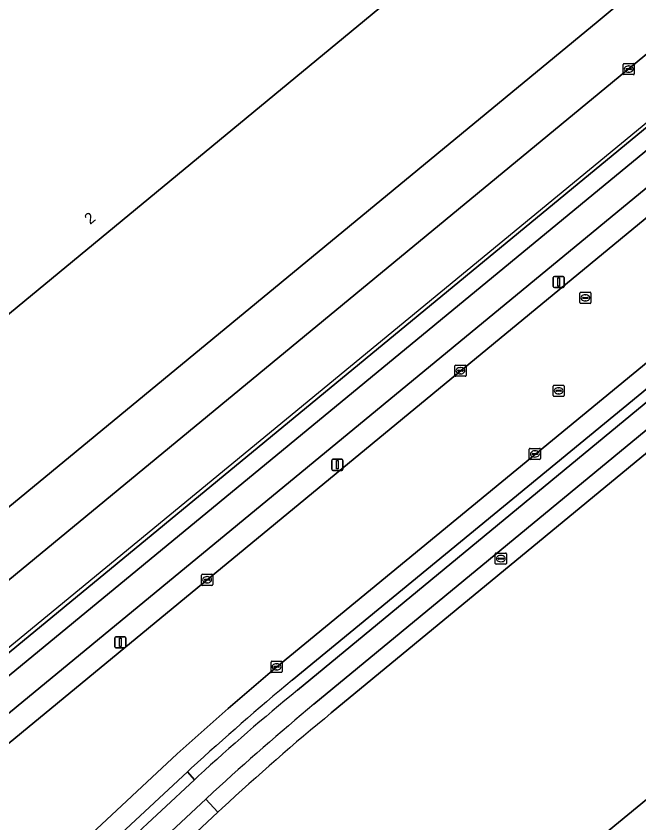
# Model space of a CAD drawing. Extents: x 156141 to 158132, y 385651 to 388333.
# Drawn here: x 157302.8 to 157358.7, y 386521.5 to 386593.9 of the extents above; entities that cross this region are included whole.
import ezdxf

# ---------------------------------------------------------------- set-up
doc = ezdxf.new("R2010")
doc.units = 0
for name, color, linetype in [('IMGEO_Berm_groen', 7, 'Continuous'), ('IMGEO_Berm_open', 7, 'Continuous'), ('IMGEO_Brandkraan', 7, 'Continuous'), ('IMGEO_Erf', 7, 'Continuous'), ('IMGEO_Fietspad_gesloten', 7, 'Continuous'), ('IMGEO_Hek', 7, 'Continuous'), ('IMGEO_Kolk', 7, 'Continuous'), ('IMGEO_Lichtmast', 7, 'Continuous'), ('IMGEO_Pand', 7, 'Continuous'), ('IMGEO_Pand_nummerreeks', 7, 'Continuous'), ('IMGEO_Parkeervlak_open', 7, 'Continuous'), ('IMGEO_Rijbaan_lokaal_gesloten', 7, 'Continuous'), ('IMGEO_Rioolput', 7, 'Continuous'), ('IMGEO_Voetpad_open', 7, 'Continuous')]:
    doc.layers.add(name, color=color, linetype=linetype)

msp = doc.modelspace()

# ---------------------------------------------------------------- linework, layer by layer
at = {"layer": 'IMGEO_Berm_groen'}
msp.add_lwpolyline([(157382.602, 386594.939), (157381.274, 386596.535), (157296.442, 386526.682), (157297.766, 386525.075)], close=True, dxfattribs=at)
at = {"layer": 'IMGEO_Berm_open'}
for points in [[(157328.045, 386533.38), (157394.438, 386588.131)], [(157376.34, 386574.366), (157372.407, 386571.122), (157327.556, 386534.294)], [(157318.496, 386526.391), (157318.148, 386526.066), (157318.786, 386525.342), (157319.149, 386525.681)]]:
    msp.add_lwpolyline(points, dxfattribs=at)
msp.add_lwpolyline([(157318.786, 386525.342), (157318.148, 386526.066), (157312.211, 386520.524), (157312.866, 386519.814)], close=True, dxfattribs=at)
for centre, radius, start, end in [((157539.191, 386282.531), 328.898, 130.0508, 132.14531), ((157438.082, 386397.245), 175.045, 128.94858, 132.8002)]:
    msp.add_arc(centre, radius, start, end, dxfattribs=at)
at = {"layer": 'IMGEO_Brandkraan'}
for p, q in [((157345.805, 386544.773), (157345.805, 386545.625)), ((157345.88, 386545.699), (157346.732, 386545.699)), ((157346.293, 386545.479), (157346.318, 386545.479)), ((157346.806, 386545.625), (157346.806, 386544.773)), ((157346.732, 386544.699), (157345.88, 386544.699)), ((157346.064, 386545.193), (157346.064, 386545.205)), ((157346.502, 386545.156), (157346.104, 386545.156)), ((157346.107, 386545.242), (157346.505, 386545.242)), ((157346.316, 386544.919), (157346.291, 386544.919)), ((157346.548, 386545.205), (157346.548, 386545.193))]:
    msp.add_line(p, q, dxfattribs=at)
for points in [[(157345.805, 386544.773), (157345.805, 386545.625)], [(157345.88, 386545.699), (157346.732, 386545.699)], [(157346.806, 386545.625), (157346.806, 386544.773)], [(157346.732, 386544.699), (157345.88, 386544.699)]]:
    msp.add_lwpolyline(points, dxfattribs=at)
for centre, radius, start, end in [((157345.882, 386545.623), 0.0765, 91.55205, 178.44795), ((157345.882, 386545.623), 0.0765, 91.55205, 178.44795), ((157346.73, 386545.623), 0.0765, 1.55205, 88.44795), ((157346.73, 386545.623), 0.0765, 1.55205, 88.44795), ((157345.882, 386544.775), 0.0765, 181.55205, 268.44795), ((157345.882, 386544.775), 0.0765, 181.55205, 268.44795), ((157346.104, 386545.202), 0.0403, 85.87752, 175.75265), ((157346.101, 386545.192), 0.0366, 178.93798, 274.71019), ((157346.505, 386545.199), 0.043, 264.86636, 352.45326), ((157346.509, 386545.204), 0.0386, 1.73085, 96.63898), ((157346.73, 386544.775), 0.0765, 271.55205, 358.44795), ((157346.73, 386544.775), 0.0765, 271.55205, 358.44795)]:
    msp.add_arc(centre, radius, start, end, dxfattribs=at)
for centre, major_axis, ratio, start_param, end_param in [((157346.292, 386545.199), (-0.387, 0.002), 0.722429, 4.712389, 7.853982), ((157346.317, 386545.199), (-0.39, 0.002), 0.717154, 1.570796, 4.712389)]:
    msp.add_ellipse(centre, major_axis=major_axis, ratio=ratio, start_param=start_param, end_param=end_param, dxfattribs=at)
at = {"layer": 'IMGEO_Erf'}
for points in [[(157305.192, 386652.34), (157328.566, 386623.963), (157330.054, 386625.191), (157333.041, 386621.572), (157326.951, 386616.541), (157327.989, 386615.321), (157327.85, 386615.21), (157325.922, 386617.509), (157324.723, 386616.531), (157326.63, 386614.203), (157339.73, 386598.213), (157295.954, 386562.121), (157267.479, 386596.651), (157267.16, 386597.038), (157261.752, 386592.577), (157272.198, 386579.91), (157282.729, 386567.139), (157237.494, 386529.843)], [(157426.002, 386606.547), (157415.889, 386601.234), (157395.717, 386584.595), (157331.077, 386531.339)], [(157374.788, 386603.209), (157247.853, 386498.572)], [(157244.527, 386502.398), (157355.06, 386593.473), (157357.572, 386595.586)], [(157227.04, 386499.657), (157223.804, 386503.613), (157223.415, 386503.292), (157220.027, 386500.497), (157216.845, 386504.354), (157216.725, 386504.499), (157208.034, 386497.245), (157213.099, 386491.073), (157226.605, 386474.613), (157226.82, 386474.791), (157233.891, 386480.604), (157236.032, 386482.364), (157257.451, 386500), (157293.78, 386529.914), (157370.157, 386592.804)], [(157297.7, 386472.957), (157408.986, 386564.286), (157406.345, 386567.501), (157408.054, 386569.305), (157409.595, 386570.572), (157409.296, 386570.978), (157413.216, 386574.145), (157432.072, 386589.667)], [(157321.28, 386522.788), (157320.885, 386522.419), (157315.585, 386517.47), (157309.052, 386511.37), (157296.875, 386500), (157254.307, 386460.253), (157244.415, 386451.012)]]:
    msp.add_lwpolyline(points, dxfattribs=at)
msp.add_arc((157459.556, 386374.251), 202.937, 129.27903, 132.95107, dxfattribs=at)
at = {"layer": 'IMGEO_Fietspad_gesloten'}
for points in [[(157329.519, 386532.125), (157395.183, 386586.243), (157420.831, 386607.378), (157421.754, 386607.263), (157440.244, 386622.337), (157440.347, 386623.46), (157455.216, 386635.714), (157460.748, 386640.332), (157459.614, 386641.71), (157440.559, 386626.134), (157436.323, 386622.672), (157424.344, 386612.801), (157418.226, 386607.639), (157394.438, 386588.131), (157328.045, 386533.38)], [(157264.038, 386500), (157296.442, 386526.682), (157381.274, 386596.535), (157379.639, 386598.545), (157294.792, 386528.687), (157259.949, 386500), (157236.74, 386480.891), (157225.904, 386471.963), (157216.572, 386464.306), (157144.792, 386405.245)], [(157319.149, 386525.681), (157318.786, 386525.342), (157312.866, 386519.814), (157306.779, 386514.131), (157291.645, 386500), (157251.933, 386462.92), (157239.857, 386451.669), (157234.331, 386446.076), (157226.974, 386437.945), (157221.6, 386431.989), (157216.385, 386426.46), (157218.105, 386424.875), (157235.961, 386444.744)], [(157242.992, 386451.871), (157253.209, 386461.424), (157294.518, 386500), (157308.027, 386512.615), (157314.484, 386518.644), (157319.804, 386523.613), (157320.476, 386524.24)]]:
    msp.add_lwpolyline(points, dxfattribs=at)
for centre, radius, start, end in [((157438.082, 386397.245), 175.045, 128.94858, 132.8002), ((157491.803, 386336.88), 253.883, 129.73269, 132.4406)]:
    msp.add_arc(centre, radius, start, end, dxfattribs=at)
at = {"layer": 'IMGEO_Hek'}
msp.add_lwpolyline([(157370.513, 386593.457), (157256.854, 386500)], dxfattribs=at)
at = {"layer": 'IMGEO_Kolk'}
for p, q in [((157357.292, 386588.735), (157357.292, 386589.587)), ((157357.367, 386589.661), (157358.219, 386589.661)), ((157358.293, 386589.587), (157358.293, 386588.735)), ((157357.551, 386589.155), (157357.551, 386589.167)), ((157357.989, 386589.118), (157357.591, 386589.118)), ((157357.594, 386589.204), (157357.992, 386589.204)), ((157357.803, 386588.881), (157357.778, 386588.881)), ((157357.78, 386589.441), (157357.805, 386589.441)), ((157358.035, 386589.167), (157358.035, 386589.155)), ((157358.219, 386588.661), (157357.367, 386588.661)), ((157342.176, 386561.652), (157342.176, 386562.504)), ((157342.251, 386562.578), (157343.103, 386562.578)), ((157342.435, 386562.072), (157342.435, 386562.084)), ((157342.873, 386562.035), (157342.475, 386562.035)), ((157342.478, 386562.121), (157342.876, 386562.121)), ((157342.664, 386562.358), (157342.689, 386562.358)), ((157342.919, 386562.084), (157342.919, 386562.072)), ((157343.177, 386562.504), (157343.177, 386561.652)), ((157343.103, 386561.578), (157342.251, 386561.578)), ((157342.687, 386561.798), (157342.662, 386561.798)), ((157348.863, 386554.178), (157348.863, 386555.03)), ((157348.938, 386555.104), (157349.79, 386555.104)), ((157349.351, 386554.884), (157349.376, 386554.884)), ((157349.864, 386555.03), (157349.864, 386554.178)), ((157349.79, 386554.104), (157348.938, 386554.104)), ((157349.122, 386554.598), (157349.122, 386554.61)), ((157349.56, 386554.561), (157349.162, 386554.561)), ((157349.165, 386554.647), (157349.563, 386554.647)), ((157349.374, 386554.324), (157349.349, 386554.324)), ((157349.606, 386554.61), (157349.606, 386554.598)), ((157319.418, 386542.876), (157319.418, 386543.728)), ((157319.493, 386543.802), (157320.345, 386543.802)), ((157319.677, 386543.296), (157319.677, 386543.308)), ((157320.115, 386543.259), (157319.717, 386543.259)), ((157319.72, 386543.345), (157320.118, 386543.345)), ((157319.906, 386543.582), (157319.931, 386543.582)), ((157320.161, 386543.308), (157320.161, 386543.296)), ((157320.419, 386543.728), (157320.419, 386542.876)), ((157320.345, 386542.802), (157319.493, 386542.802)), ((157319.929, 386543.022), (157319.904, 386543.022)), ((157325.738, 386535.986), (157326.59, 386535.986)), ((157325.663, 386535.06), (157325.663, 386535.912)), ((157325.922, 386535.48), (157325.922, 386535.492)), ((157326.36, 386535.443), (157325.962, 386535.443)), ((157325.965, 386535.529), (157326.363, 386535.529)), ((157326.174, 386535.206), (157326.149, 386535.206)), ((157326.151, 386535.766), (157326.176, 386535.766)), ((157326.406, 386535.492), (157326.406, 386535.48)), ((157326.664, 386535.912), (157326.664, 386535.06)), ((157326.59, 386534.986), (157325.738, 386534.986))]:
    msp.add_line(p, q, dxfattribs=at)
for points in [[(157357.292, 386588.735), (157357.292, 386589.587)], [(157357.367, 386589.661), (157358.219, 386589.661)], [(157358.293, 386589.587), (157358.293, 386588.735)], [(157358.219, 386588.661), (157357.367, 386588.661)], [(157342.176, 386561.652), (157342.176, 386562.504)], [(157342.251, 386562.578), (157343.103, 386562.578)], [(157343.177, 386562.504), (157343.177, 386561.652)], [(157343.103, 386561.578), (157342.251, 386561.578)], [(157348.863, 386554.178), (157348.863, 386555.03)], [(157348.938, 386555.104), (157349.79, 386555.104)], [(157349.864, 386555.03), (157349.864, 386554.178)], [(157349.79, 386554.104), (157348.938, 386554.104)], [(157319.418, 386542.876), (157319.418, 386543.728)], [(157319.493, 386543.802), (157320.345, 386543.802)], [(157320.419, 386543.728), (157320.419, 386542.876)], [(157320.345, 386542.802), (157319.493, 386542.802)], [(157325.738, 386535.986), (157326.59, 386535.986)], [(157325.663, 386535.06), (157325.663, 386535.912)], [(157326.664, 386535.912), (157326.664, 386535.06)], [(157326.59, 386534.986), (157325.738, 386534.986)]]:
    msp.add_lwpolyline(points, dxfattribs=at)
for centre, radius, start, end in [((157357.369, 386589.585), 0.0765, 91.55205, 178.44795), ((157357.369, 386589.585), 0.0765, 91.55205, 178.44795), ((157358.217, 386589.585), 0.0765, 1.55205, 88.44795), ((157358.217, 386589.585), 0.0765, 1.55205, 88.44795), ((157357.591, 386589.164), 0.0403, 85.87752, 175.75265), ((157357.588, 386589.154), 0.0366, 178.93798, 274.71019), ((157357.992, 386589.161), 0.043, 264.86636, 352.45326), ((157357.996, 386589.166), 0.0386, 1.73085, 96.63898), ((157357.369, 386588.737), 0.0765, 181.55205, 268.44795), ((157357.369, 386588.737), 0.0765, 181.55205, 268.44795), ((157358.217, 386588.737), 0.0765, 271.55205, 358.44795), ((157358.217, 386588.737), 0.0765, 271.55205, 358.44795), ((157342.253, 386562.502), 0.0765, 91.55205, 178.44795), ((157342.253, 386562.502), 0.0765, 91.55205, 178.44795), ((157342.475, 386562.081), 0.0403, 85.87752, 175.75265), ((157342.472, 386562.071), 0.0366, 178.93798, 274.71019), ((157342.876, 386562.078), 0.043, 264.86636, 352.45326), ((157342.88, 386562.083), 0.0386, 1.73085, 96.63898), ((157343.101, 386562.502), 0.0765, 1.55205, 88.44795), ((157343.101, 386562.502), 0.0765, 1.55205, 88.44795), ((157342.253, 386561.654), 0.0765, 181.55205, 268.44795), ((157342.253, 386561.654), 0.0765, 181.55205, 268.44795), ((157343.101, 386561.654), 0.0765, 271.55205, 358.44795), ((157343.101, 386561.654), 0.0765, 271.55205, 358.44795), ((157348.94, 386555.028), 0.0765, 91.55205, 178.44795), ((157348.94, 386555.028), 0.0765, 91.55205, 178.44795), ((157349.788, 386555.028), 0.0765, 1.55205, 88.44795), ((157349.788, 386555.028), 0.0765, 1.55205, 88.44795), ((157348.94, 386554.18), 0.0765, 181.55205, 268.44795), ((157348.94, 386554.18), 0.0765, 181.55205, 268.44795), ((157349.162, 386554.607), 0.0403, 85.87752, 175.75265), ((157349.159, 386554.597), 0.0366, 178.93798, 274.71019), ((157349.563, 386554.604), 0.043, 264.86636, 352.45326), ((157349.567, 386554.609), 0.0386, 1.73085, 96.63898), ((157349.788, 386554.18), 0.0765, 271.55205, 358.44795), ((157349.788, 386554.18), 0.0765, 271.55205, 358.44795), ((157319.495, 386543.726), 0.0765, 91.55205, 178.44795), ((157319.495, 386543.726), 0.0765, 91.55205, 178.44795), ((157319.717, 386543.305), 0.0403, 85.87752, 175.75265), ((157319.714, 386543.295), 0.0366, 178.93798, 274.71019), ((157320.118, 386543.302), 0.043, 264.86636, 352.45326), ((157320.122, 386543.307), 0.0386, 1.73085, 96.63898), ((157320.343, 386543.726), 0.0765, 1.55205, 88.44795), ((157320.343, 386543.726), 0.0765, 1.55205, 88.44795), ((157319.495, 386542.878), 0.0765, 181.55205, 268.44795), ((157319.495, 386542.878), 0.0765, 181.55205, 268.44795), ((157320.343, 386542.878), 0.0765, 271.55205, 358.44795), ((157320.343, 386542.878), 0.0765, 271.55205, 358.44795), ((157325.74, 386535.91), 0.0765, 91.55205, 178.44795), ((157325.74, 386535.91), 0.0765, 91.55205, 178.44795), ((157326.588, 386535.91), 0.0765, 1.55205, 88.44795), ((157326.588, 386535.91), 0.0765, 1.55205, 88.44795), ((157325.962, 386535.489), 0.0403, 85.87752, 175.75265), ((157325.959, 386535.479), 0.0366, 178.93798, 274.71019), ((157326.363, 386535.486), 0.043, 264.86636, 352.45326), ((157326.367, 386535.491), 0.0386, 1.73085, 96.63898), ((157325.74, 386535.062), 0.0765, 181.55205, 268.44795), ((157325.74, 386535.062), 0.0765, 181.55205, 268.44795), ((157326.588, 386535.062), 0.0765, 271.55205, 358.44795), ((157326.588, 386535.062), 0.0765, 271.55205, 358.44795)]:
    msp.add_arc(centre, radius, start, end, dxfattribs=at)
for centre, major_axis, ratio, start_param, end_param in [((157357.779, 386589.161), (-0.387, 0.002), 0.722429, 4.712389, 7.853982), ((157357.804, 386589.161), (-0.39, 0.002), 0.717154, 1.570796, 4.712389), ((157342.663, 386562.078), (-0.387, 0.002), 0.722429, 4.712389, 7.853982), ((157342.688, 386562.078), (-0.39, 0.002), 0.717154, 1.570796, 4.712389), ((157349.35, 386554.604), (-0.387, 0.002), 0.722429, 4.712389, 7.853982), ((157349.375, 386554.604), (-0.39, 0.002), 0.717154, 1.570796, 4.712389), ((157319.905, 386543.302), (-0.387, 0.002), 0.722429, 4.712389, 7.853982), ((157319.93, 386543.302), (-0.39, 0.002), 0.717154, 1.570796, 4.712389), ((157326.15, 386535.486), (-0.387, 0.002), 0.722429, 4.712389, 7.853982), ((157326.175, 386535.486), (-0.39, 0.002), 0.717154, 1.570796, 4.712389)]:
    msp.add_ellipse(centre, major_axis=major_axis, ratio=ratio, start_param=start_param, end_param=end_param, dxfattribs=at)
at = {"layer": 'IMGEO_Lichtmast'}
for p, q in [((157351.016, 386569.645), (157351.016, 386570.445)), ((157351.016, 386570.445), (157351.016, 386569.645)), ((157351.116, 386570.545), (157351.906, 386570.545)), ((157351.906, 386570.545), (157351.116, 386570.545)), ((157352.006, 386570.445), (157352.006, 386569.645)), ((157352.006, 386569.645), (157352.006, 386570.445)), ((157351.906, 386569.545), (157351.116, 386569.545)), ((157351.116, 386569.545), (157351.906, 386569.545)), ((157331.217, 386554.125), (157332.007, 386554.125)), ((157332.007, 386554.125), (157331.217, 386554.125)), ((157331.117, 386553.225), (157331.117, 386554.025)), ((157331.117, 386554.025), (157331.117, 386553.225)), ((157332.107, 386554.025), (157332.107, 386553.225)), ((157332.107, 386553.225), (157332.107, 386554.025)), ((157332.007, 386553.125), (157331.217, 386553.125)), ((157331.217, 386553.125), (157332.007, 386553.125)), ((157311.623, 386537.29), (157311.623, 386538.09)), ((157311.623, 386538.09), (157311.623, 386537.29)), ((157311.723, 386538.19), (157312.513, 386538.19)), ((157312.513, 386538.19), (157311.723, 386538.19)), ((157312.613, 386538.09), (157312.613, 386537.29)), ((157312.613, 386537.29), (157312.613, 386538.09)), ((157312.513, 386537.19), (157311.723, 386537.19)), ((157311.723, 386537.19), (157312.513, 386537.19))]:
    msp.add_line(p, q, dxfattribs=at)
for points in [[(157351.436, 386570.42), (157351.586, 386570.42), (157351.586, 386569.67), (157351.436, 386569.67), (157351.436, 386570.42)], [(157331.537, 386554), (157331.687, 386554), (157331.687, 386553.25), (157331.537, 386553.25), (157331.537, 386554)], [(157312.043, 386538.065), (157312.193, 386538.065), (157312.193, 386537.315), (157312.043, 386537.315), (157312.043, 386538.065)]]:
    msp.add_lwpolyline(points, dxfattribs=at)
for centre, start, end in [((157351.116, 386570.445), 90, 180), ((157351.116, 386570.445), 90, 180), ((157351.906, 386570.445), 0, 90), ((157351.906, 386570.445), 360, 90), ((157351.116, 386569.645), 180, 270), ((157351.116, 386569.645), 180, 270), ((157351.906, 386569.645), 270, 0), ((157351.906, 386569.645), 270, 0), ((157331.217, 386554.025), 90, 180), ((157331.217, 386554.025), 90, 180), ((157332.007, 386554.025), 0, 90), ((157332.007, 386554.025), 360, 90), ((157331.217, 386553.225), 180, 270), ((157331.217, 386553.225), 180, 270), ((157332.007, 386553.225), 270, 0), ((157332.007, 386553.225), 270, 0), ((157311.723, 386538.09), 90, 180), ((157311.723, 386538.09), 90, 180), ((157312.513, 386538.09), 0, 90), ((157312.513, 386538.09), 360, 90), ((157311.723, 386537.29), 180, 270), ((157311.723, 386537.29), 180, 270), ((157312.513, 386537.29), 270, 0), ((157312.513, 386537.29), 270, 0)]:
    msp.add_arc(centre, 0.1, start, end, dxfattribs=at)
at = {"layer": 'IMGEO_Pand'}
msp.add_lwpolyline([(157237.494, 386529.843), (157282.729, 386567.139), (157272.198, 386579.91), (157261.752, 386592.577), (157267.16, 386597.038), (157267.479, 386596.651), (157295.954, 386562.121), (157339.73, 386598.213), (157326.63, 386614.203), (157324.723, 386616.531), (157325.922, 386617.509), (157327.85, 386615.21), (157327.989, 386615.321), (157326.951, 386616.541), (157333.041, 386621.572), (157330.054, 386625.191), (157328.566, 386623.963), (157305.192, 386652.34)], dxfattribs=at)
at = {"layer": 'IMGEO_Parkeervlak_open'}
for points in [[(157377.251, 386577.456), (157325.992, 386535.328), (157321.807, 386531.733), (157317.225, 386527.675), (157305.013, 386516.275), (157287.58, 386500), (157249.93, 386464.852), (157230.038, 386446.321)], [(157327.556, 386534.294), (157372.407, 386571.122), (157376.34, 386574.366)], [(157231.488, 386446.852), (157232.878, 386446.849), (157233.43, 386447.026), (157233.598, 386447.152), (157251.164, 386463.536), (157290.225, 386500), (157306.163, 386514.878), (157312.211, 386520.524), (157318.148, 386526.066), (157318.496, 386526.391)]]:
    msp.add_lwpolyline(points, dxfattribs=at)
msp.add_arc((157539.191, 386282.531), 328.898, 130.0508, 132.14531, dxfattribs=at)
at = {"layer": 'IMGEO_Rijbaan_lokaal_gesloten'}
for points in [[(157429.506, 386633.553), (157391.761, 386602.481), (157387.245, 386598.763), (157382.602, 386594.939), (157297.766, 386525.075), (157267.318, 386500), (157239.52, 386477.108)], [(157247.853, 386498.572), (157374.788, 386603.209)], [(157357.572, 386595.586), (157355.06, 386593.473), (157244.527, 386502.398)], [(157432.072, 386589.667), (157413.216, 386574.145), (157409.296, 386570.978), (157409.595, 386570.572), (157408.054, 386569.305), (157406.345, 386567.501), (157408.986, 386564.286), (157297.7, 386472.957)], [(157287.58, 386500), (157305.013, 386516.275), (157317.225, 386527.675), (157321.807, 386531.733), (157325.992, 386535.328), (157377.251, 386577.456), (157379.615, 386579.4)]]:
    msp.add_lwpolyline(points, dxfattribs=at)
at = {"layer": 'IMGEO_Rioolput'}
for p, q in [((157353.396, 386568.191), (157353.396, 386569.043)), ((157353.471, 386569.117), (157354.323, 386569.117)), ((157353.655, 386568.611), (157353.655, 386568.623)), ((157354.093, 386568.574), (157353.695, 386568.574)), ((157353.698, 386568.66), (157354.096, 386568.66)), ((157353.884, 386568.897), (157353.909, 386568.897)), ((157354.139, 386568.623), (157354.139, 386568.611)), ((157354.397, 386569.043), (157354.397, 386568.191)), ((157354.323, 386568.117), (157353.471, 386568.117)), ((157353.907, 386568.337), (157353.882, 386568.337)), ((157350.999, 386559.846), (157350.999, 386560.698)), ((157351.074, 386560.772), (157351.926, 386560.772)), ((157351.487, 386560.552), (157351.512, 386560.552)), ((157352, 386560.698), (157352, 386559.846)), ((157351.258, 386560.266), (157351.258, 386560.278)), ((157351.696, 386560.229), (157351.298, 386560.229)), ((157351.301, 386560.315), (157351.699, 386560.315)), ((157351.51, 386559.992), (157351.485, 386559.992)), ((157351.742, 386560.278), (157351.742, 386560.266)), ((157351.926, 386559.772), (157351.074, 386559.772))]:
    msp.add_line(p, q, dxfattribs=at)
for points in [[(157353.396, 386568.191), (157353.396, 386569.043)], [(157353.471, 386569.117), (157354.323, 386569.117)], [(157354.397, 386569.043), (157354.397, 386568.191)], [(157354.323, 386568.117), (157353.471, 386568.117)], [(157350.999, 386559.846), (157350.999, 386560.698)], [(157351.074, 386560.772), (157351.926, 386560.772)], [(157352, 386560.698), (157352, 386559.846)], [(157351.926, 386559.772), (157351.074, 386559.772)]]:
    msp.add_lwpolyline(points, dxfattribs=at)
for centre, radius, start, end in [((157353.473, 386569.041), 0.0765, 91.55205, 178.44795), ((157353.473, 386569.041), 0.0765, 91.55205, 178.44795), ((157353.695, 386568.62), 0.0403, 85.87752, 175.75265), ((157353.692, 386568.61), 0.0366, 178.93798, 274.71019), ((157354.096, 386568.617), 0.043, 264.86636, 352.45326), ((157354.1, 386568.622), 0.0386, 1.73085, 96.63898), ((157354.321, 386569.041), 0.0765, 1.55205, 88.44795), ((157354.321, 386569.041), 0.0765, 1.55205, 88.44795), ((157353.473, 386568.193), 0.0765, 181.55205, 268.44795), ((157353.473, 386568.193), 0.0765, 181.55205, 268.44795), ((157354.321, 386568.193), 0.0765, 271.55205, 358.44795), ((157354.321, 386568.193), 0.0765, 271.55205, 358.44795), ((157351.076, 386560.696), 0.0765, 91.55205, 178.44795), ((157351.076, 386560.696), 0.0765, 91.55205, 178.44795), ((157351.924, 386560.696), 0.0765, 1.55205, 88.44795), ((157351.924, 386560.696), 0.0765, 1.55205, 88.44795), ((157351.076, 386559.848), 0.0765, 181.55205, 268.44795), ((157351.076, 386559.848), 0.0765, 181.55205, 268.44795), ((157351.298, 386560.275), 0.0403, 85.87752, 175.75265), ((157351.295, 386560.265), 0.0366, 178.93798, 274.71019), ((157351.699, 386560.272), 0.043, 264.86636, 352.45326), ((157351.703, 386560.277), 0.0386, 1.73085, 96.63898), ((157351.924, 386559.848), 0.0765, 271.55205, 358.44795), ((157351.924, 386559.848), 0.0765, 271.55205, 358.44795)]:
    msp.add_arc(centre, radius, start, end, dxfattribs=at)
for centre, major_axis, ratio, start_param, end_param in [((157353.883, 386568.617), (-0.387, 0.002), 0.722429, 4.712389, 7.853982), ((157353.908, 386568.617), (-0.39, 0.002), 0.717154, 1.570796, 4.712389), ((157351.486, 386560.272), (-0.387, 0.002), 0.722429, 4.712389, 7.853982), ((157351.511, 386560.272), (-0.39, 0.002), 0.717154, 1.570796, 4.712389)]:
    msp.add_ellipse(centre, major_axis=major_axis, ratio=ratio, start_param=start_param, end_param=end_param, dxfattribs=at)
at = {"layer": 'IMGEO_Voetpad_open'}
for points in [[(157395.717, 386584.595), (157415.889, 386601.234), (157426.002, 386606.547), (157426.054, 386606.589), (157426.201, 386606.709), (157421.754, 386607.263), (157420.831, 386607.378), (157395.183, 386586.243), (157329.519, 386532.125)], [(157331.077, 386531.339), (157395.717, 386584.595)], [(157320.476, 386524.24), (157319.804, 386523.613), (157320.885, 386522.419), (157321.28, 386522.788)]]:
    msp.add_lwpolyline(points, dxfattribs=at)
for points in [[(157379.639, 386598.545), (157378.624, 386599.775), (157370.157, 386592.804), (157293.78, 386529.914), (157257.451, 386500), (157236.032, 386482.364), (157233.891, 386480.604), (157226.82, 386474.791), (157226.605, 386474.613), (157224.923, 386473.224), (157225.904, 386471.963), (157236.74, 386480.891), (157259.949, 386500), (157294.792, 386528.687)], [(157314.484, 386518.644), (157315.585, 386517.47), (157320.885, 386522.419), (157319.804, 386523.613)]]:
    msp.add_lwpolyline(points, close=True, dxfattribs=at)
for centre, radius, start, end in [((157491.803, 386336.88), 253.883, 129.73269, 132.4406), ((157459.556, 386374.251), 202.937, 129.27903, 132.95107)]:
    msp.add_arc(centre, radius, start, end, dxfattribs=at)

# ---------------------------------------------------------------- texts
at = {"layer": 'IMGEO_Pand_nummerreeks'}
msp.add_text('2', height=1, rotation=39.50544, dxfattribs=at).set_placement((157309.404, 386575.154))

doc.saveas('drawing.dxf')
